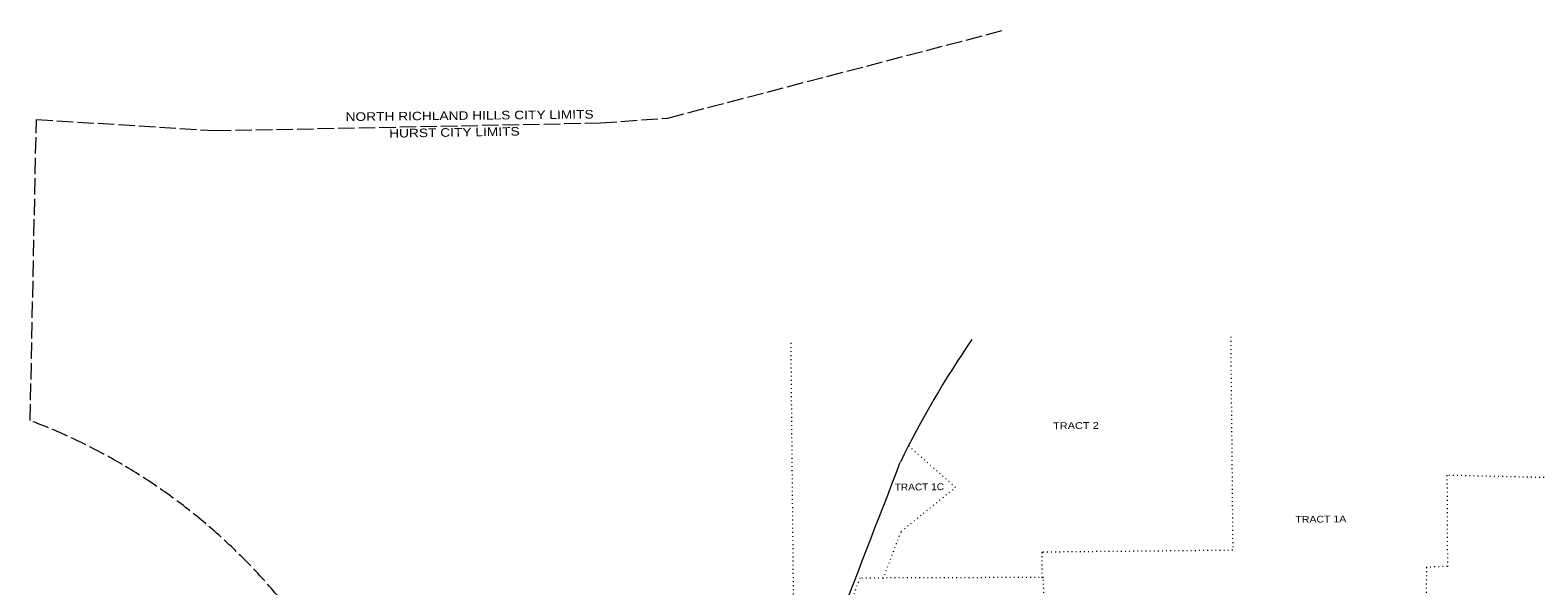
# Model space of a CAD drawing. Extents: x 2356373 to 2371954, y 6966197 to 6989612.
# Drawn here: x 2365193 to 2368714, y 6988314 to 6989612 of the extents above; entities that cross this region are included whole.
import ezdxf

# ---------------------------------------------------------------- set-up
doc = ezdxf.new("R2010")
doc.units = 0
doc.header["$LTSCALE"] = 6.4
doc.linetypes.add('DOTTED', pattern=[1.5, 0.3, -1.2])
doc.linetypes.add('LONG_DASHED', pattern=[7.5, 6, -1.5])
doc.layers.add('10', color=7, linetype='Continuous')
doc.layers.add('26', color=7, linetype='Continuous')
for name, color, linetype, lineweight in [('12', 7, 'Continuous', 13), ('15', 7, 'Continuous', 13), ('27', 7, 'LONG_DASHED', 13), ('4', 7, 'Continuous', 13), ('5', 7, 'DOTTED', 13), ('6', 7, 'DOTTED', 13)]:
    doc.layers.add(name, color=color, linetype=linetype, lineweight=lineweight)

msp = doc.modelspace()

# ---------------------------------------------------------------- linework, layer by layer
at = {"layer": '15'}
for centre, radius, start, end in [((2369202.444, 6987641.257), 2198.707, 145.41276, 154.06936), ((2245564.628, 7035256.411), 130298.933, 338.63276, 339.01946)]:
    msp.add_arc(centre, radius, start, end, dxfattribs=at)
at = {"layer": '27'}
msp.add_lwpolyline([(2365193.005, 6988699.762), (2365207.521, 6989403.435), (2365624.356, 6989377.156), (2366524.58, 6989395.223), (2366682.206, 6989406.719), (2367466.837, 6989612.023)], dxfattribs=at)
msp.add_ellipse((2364704.649, 6987389.534), major_axis=(0, 1398.955), ratio=0.996074, start_param=5.30742738, end_param=5.9251203, dxfattribs=at)
at = {"layer": '4', "linetype": 'DOTTED'}
msp.add_line((2366978.738, 6987977.019), (2366969.817, 6988885.389), dxfattribs=at)
at = {"layer": '5'}
for points in [[(2367185.211, 6988330.453), (2367227.112, 6988441.137), (2367354.071, 6988543.655), (2367242.126, 6988642.729)], [(2367568.733, 6987961.42), (2367559.084, 6988333.226), (2367130.213, 6988331.814), (2366986.125, 6987937.502), (2367021.907, 6987755.102), (2367069.049, 6987739.369), (2367025.372, 6987605.977), (2367212.069, 6987529.832), (2367257.375, 6987599.158)]]:
    msp.add_lwpolyline(points, dxfattribs=at)
at = {"layer": '6'}
for points in [[(2367996.443, 6988895.473), (2368001.342, 6988396.654), (2367555.504, 6988392.275), (2367555.115, 6988330.187)], [(2368907.082, 6988602.2), (2368728.48, 6988566.553), (2368501.487, 6988571.922), (2368502.58, 6988358.889), (2368453.608, 6988357.209), (2368452.677, 6988248.529), (2368261.701, 6988251.252), (2368261.855, 6988133.884), (2368184.907, 6988130.629), (2368186.832, 6987934.5), (2368048.888, 6987932.745), (2368047.002, 6987717.584), (2367829.102, 6987713.345), (2367828.946, 6987525.793), (2368298.808, 6987527.009), (2368300.251, 6987176.518)]]:
    msp.add_lwpolyline(points, dxfattribs=at)

# ---------------------------------------------------------------- texts
at = {"layer": '10', "width": 1.1}
msp.add_text('TRACT 1C', height=15.99, rotation=0.563, dxfattribs=at).set_placement((2367212.181, 6988536.264))
at = {"layer": '12'}
for s, width, p in [('TRACT 2', 1.2, (2367581.676, 6988679.456)), ('TRACT 1A', 1.15, (2368147.672, 6988460.875))]:
    msp.add_text(s, height=15.99, rotation=0.563, dxfattribs=dict(at, width=width)).set_placement(p)
at = {"layer": '26', "width": 1.2}
for s, rotation, p in [('NORTH RICHLAND HILLS CITY LIMITS', 0.584, (2365929.647, 6989399.683)), ('HURST CITY LIMITS', 0.948, (2366031.453, 6989360.737))]:
    msp.add_text(s, height=19.99, rotation=rotation, dxfattribs=at).set_placement(p)

doc.saveas('drawing.dxf')
